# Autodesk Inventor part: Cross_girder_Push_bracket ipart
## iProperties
Shininess: 69.0
Length Units: 11269
Angle Units: 11279
Time Units: 11290
Mass Units: 11283
Length Display Precision: 3
Angle Display Precision: 2
Created: 2001-06
Part Number: Cross_girder_Push_bracket ipart
Material: Standard
Document SubType Name: Modellieren
Designer: dl
Density: 1 g/cm^3
Density: 0.0
Volumn: 0.0
Area: 0.0
PropertySet Name: Model Information
Control State: 0
Master: False
Checked Out: False
Author: dl
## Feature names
1. Sweep1
2. Extrusion1
3. Mirror1
4. Extrusion2
5. Rectangular Pattern1
6. Mirror2
